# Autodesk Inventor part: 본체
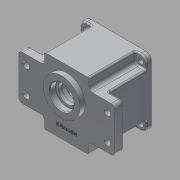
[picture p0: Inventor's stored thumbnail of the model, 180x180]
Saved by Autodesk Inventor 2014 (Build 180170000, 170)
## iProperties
Created: 2015-07
Part Number: 본체
Material: 알루미늄 6061
Document SubType Name: Modeling
Designer: Administrator
Density: 2.71 g/cm^3
Appearance: 알루미늄 - 평지
Mass: 705.342 g
Surface Area: 674.823 cm^2
Volume: 260.274 cm^3
Author: Administrator
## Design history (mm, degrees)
sketch "스케치1"
  geometry: L1 (45, 45)-(-45, 45); L2 (-45, 45)-(-45, -45); L3 (-45, -45)-(45, -45); L4 (45, -45)-(45, 45); L5 (45, 45)-(-45, -45); L6 (-45, 45)-(45, -45); 1 further point
  constraints: 12 end point, 2 midpoint, 2 parallel, 1 horizontal, 1 perpendicular
  dimensions: "d0" = 90 distance of L3.end L2.end; "d1" = 90 distance of L2.end L1.end
extrude "돌출1" new body sketch "스케치1" distance "d2" = 70; taper "d3" = 0 deg
sketch "스케치2"
  geometry: L1 (45, 45)-(30, 45); L2 (30, 45)-(30, 30); L3 (30, 30)-(45, 30); L4 (45, 30)-(45, 45); L5 (-45, 45)-(-30, 45); L6 (-30, 45)-(-30, 30); L7 (-30, 30)-(-45, 30); L8 (-45, 30)-(-45, 45); L9 (-45, -45)-(-30, -45); L10 (-30, -45)-(-30, -30); L11 (-30, -30)-(-45, -30); L12 (-45, -30)-(-45, -45); L13 (45, -45)-(30, -45); L14 (30, -45)-(30, -30); L15 (30, -30)-(45, -30); L16 (45, -30)-(45, -45); 1 further point
  constraints: 32 end point, 8 parallel, 4 horizontal, 4 perpendicular
  dimensions: "d4" = 15 distance of L3.end L2.end; "d5" = 15 distance of L2.end L1.end; "d6" = 15 distance of L6.end L7.end; "d7" = 15 distance of L5.end L6.end; "d8" = 15 distance of L11.end L10.end; "d9" = 15 distance of L10.end L9.end; "d10" = 15 distance of L14.end L15.end; "d11" = 15 distance of L15.end L13.start
extrude "돌출2" cut sketch "스케치2" distance "d12" = 63; taper "d13" = 0 deg
node "작업 평면1"
sketch "스케치3"
  geometry: L1 (65, 30)-(-65, 30); L2 (-65, 30)-(-65, -30); L3 (-65, -30)-(65, -30); L4 (65, -30)-(65, 30); L5 (65, 30)-(-65, -30); L6 (-65, 30)-(65, -30); 1 further point
  constraints: 12 end point, 2 midpoint, 2 parallel, 1 horizontal, 1 perpendicular
  dimensions: "d15" = 130 distance of L3.end L2.end; "d16" = 60 distance of L2.end L1.end
extrude "돌출3" join sketch "스케치3" distance "d17" = 12; taper "d18" = 0 deg
sketch "스케치4"
  geometry: 5 further points
  constraints: 2 horizontal alignment, 2 vertical alignment
  dimensions: "d19" = 74 distance of point (37, 37) point (-37, 37); "d20" = 37 horizontal distance of point (0, 0) point (-37, 37); "d21" = 74 distance of point (-37, -37) point (-37, 37); "d22" = 37 horizontal distance of point (0, 0) point (-37, -37)
hole "구멍1" sketch "스케치4" at (-37, 37), (-37, -37), (37, -37), (37, 37) diameter "d23" = 7; stored, may be unused: countersink angle "d27" = 90 deg, drill point angle "d29" = 118 deg; dims "d24" = 6, "d25" = 4, "d26" = 2, "d28" = 8
sketch "스케치5"
  geometry: 5 further points
  constraints: 2 horizontal alignment, 2 vertical alignment
  dimensions: "d30" = 110 distance of point (55, -17.5) point (-55, -17.5); "d31" = 55 horizontal distance of point (0, 0) point (-55, -17.5); "d32" = 35 distance of point (-55, 17.5) point (-55, -17.5); "d33" = 17.5 vertical distance of point (0, 0) point (-55, 17.5)
hole "구멍2" sketch "스케치5" at (-55, 17.5), (-55, -17.5), (55, -17.5), (55, 17.5) diameter "d34" = 9; stored, may be unused: countersink angle "d38" = 90 deg, drill point angle "d40" = 118 deg; dims "d35" = 6, "d36" = 4, "d37" = 2, "d39" = 8
sketch "스케치6"
  geometry: C1 r 40 at (0, 0); 1 further point
  constraints: 1 centre point, 1 coincident
  dimensions: "d41" = 80 diameter of C1
extrude "돌출4" cut sketch "스케치6" distance "d42" = 9; taper "d43" = 0 deg
sketch "스케치7"
  geometry: C1 r 40 at (0, 0) reference; C2 r 39 at (0, 0)
  constraints: 1 centre point, 1 coincident
  dimensions: "d44" = 78 diameter of C2
extrude "돌출5" cut sketch "스케치7" distance "d45" = 52; taper "d46" = 0 deg
sketch "스케치8"
  geometry: C1 r 25 at (0, 11); 1 further point
  constraints: 1 centre point, 1 vertical alignment
  dimensions: "d47" = 11 distance of C1.centre point (0, 0); "d48" = 50 diameter of C1
extrude "돌출6" join sketch "스케치8" distance "d49" = 7; taper "d50" = 0 deg
sketch "스케치9"
  geometry: C1 r 25 at (0, 0) reference; 2 further points
  constraints: 1 coincident
hole "구멍3" sketch "스케치9" at (0, 0) diameter "d51" = 25; stored, may be unused: countersink angle "d55" = 90 deg, drill point angle "d57" = 0 deg; dims "d52" = 6, "d53" = 32, "d54" = 8, "d56" = 13
sketch "스케치11"
  geometry: C1 r 17.5 at (0, -11) reference; C2 r 20.5 at (0, -11)
  constraints: 1 centre point, 1 coincident
  dimensions: "d61" = 41 diameter of C2
extrude "돌출8" join sketch "스케치11" distance "d62" = 7; taper "d63" = 0 deg
sketch "스케치12"
  geometry: C1 r 39 at (0, 0) reference; C2 r 14 at (0, 20)
  constraints: 1 centre point, 1 vertical alignment
  dimensions: "d64" = 28 diameter of C2; "d65" = 20 distance of C1.centre C2.centre
extrude "돌출9" join sketch "스케치12" distance "d66" = 7; taper "d67" = 0 deg
sketch "스케치13"
  geometry: C1 r 11 at (0, 20); A1 r 14 centre (0, 20) between (7.402, 8.117) and (-7.402, 8.117) reference; 1 further point
  constraints: 1 centre point, 1 coincident
  dimensions: "d68" = 22 diameter of C1
extrude "돌출10" cut sketch "스케치13" distance "d69" = 7; taper "d70" = 0 deg
sketch "스케치14"
  geometry: C1 r 11 at (0, 0) reference; C2 r 9.5 at (0, 0); 1 further point
  constraints: 1 centre point, 1 coincident
  dimensions: "d71" = 19 diameter of C2
extrude "돌출11" cut sketch "스케치14" distance "d72" = 1; taper "d73" = 0 deg
sketch "스케치15"
  geometry: C1 r 12.5 at (0, 0) reference; C2 r 17.5 at (0, 0); 1 further point
  constraints: 1 centre point, 1 coincident
  dimensions: "d74" = 35 diameter of C2
extrude "돌출12" cut sketch "스케치15" distance "d75" = 10; taper "d76" = 0 deg
sketch "스케치16"
  geometry: L1 (0, 0)-(-24.749, -24.749); L2 (0, 0)-(-35, 0); L3 (-21.758, -27.415)-(-24.603, -30.26); L4 (-25.314, -30.971)-(-27.808, -33.464); L5 (-27.415, -21.758)-(-30.26, -24.603); L6 (-30.971, -25.314)-(-34.882, -29.225); C1 r 4 at (-24.749, -24.749); A1 r 39 centre (0, 0) between (-24.603, -30.26) and (-30.26, -24.603) reference; A2 r 40 centre (0, 0) between (-25.314, -30.971) and (-30.971, -25.314) reference; A3 r 35 centre (0, 0) between (-24.749, -24.749) and (-35, 0)
  constraints: 12 end point, 8 point on circle, 4 parallel, 4 tangent, 2 centre point, 2 coincident, 1 horizontal
  dimensions: "d77" = 70 diameter of A3; "d78" = 45 deg angle of L2 L1; "d79" = 4 radius of C1
extrude "돌출13" join sketch "스케치16" stored distance "d80" = 10; taper "d81" = 0 deg
sketch "스케치17"
  geometry: A1 r 4 centre (-24.749, -24.749) between (-21.763, -27.411) and (-27.411, -21.763) reference; A2 r 4 centre (-24.749, 24.749) between (-27.411, 21.763) and (-21.763, 27.411) reference; A3 r 4 centre (24.749, 24.749) between (21.763, 27.411) and (27.411, 21.763) reference; A4 r 4 centre (24.749, -24.749) between (27.411, -21.763) and (21.763, -27.411) reference; 4 further points
  constraints: 4 coincident
hole "구멍4" sketch "스케치17" at (-24.749, 24.749), (-24.749, -24.749), (24.749, -24.749), (24.749, 24.749) diameter "d85" = 3.459; stored, may be unused: countersink angle "d89" = 90 deg, drill point angle "d91" = 118 deg; dims "d86" = 12, "d87" = 32, "d88" = 8, "d90" = 15
fillet "모깎기1" dims "d92" = 0.3
fillet "모깎기2" dims "d93" = 3.5
fillet "모깎기3" dims "d94" = 2
fillet "모깎기4" dims "d95" = 3
fillet "모깎기5" dims "d96" = 2
chamfer "모따기1" distance "d97" = 1; stored, may be unused: second distance "d98" = 2, angle "d99" = 45 deg
chamfer "모따기2" distance "d100" = 1; stored, may be unused: second distance "d101" = 2, angle "d102" = 45 deg
fillet "모깎기6" dims "d103" = 0.3
fillet "모깎기7" dims "d104" = 2
fillet "모깎기8" dims "d105" = 5
fillet "모깎기9" dims "d106" = 8
fillet "모깎기10" dims "d107" = 5
fillet "모깎기11" dims "d108" = 2
sketch "스케치18"
  geometry: L1 (-28, -45)-(28, -45) reference; C1 r 25 at (0, 11) reference; 2 further points
  constraints: 1 vertical alignment, 1 other
  dimensions: "d109" = 15 distance from line of point (0, -30) L1
feature "엠보싱1" sketch "스케치18" dims "d8" = 15, "d9" = 15, "d110" = 0.5, "d111" = 0
node "솔리드1"
pattern_circular "원형 패턴1" dims angle "d83" = 360 deg
other parameters: "d14" = -12
